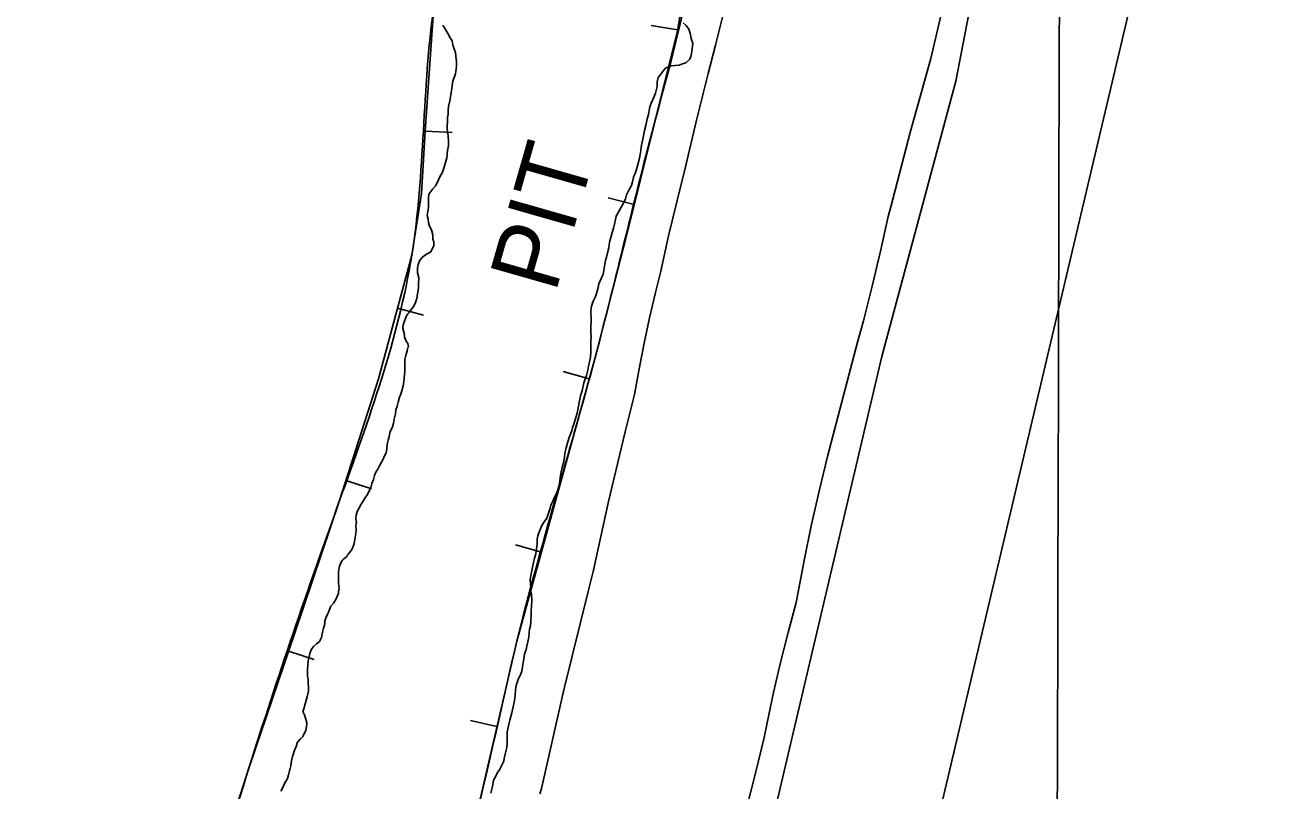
# Model space of a CAD drawing. Extents: x 3172297 to 3210190, y 958463 to 983887.
# Drawn here: x 3186026 to 3187191, y 968889 to 969598 of the extents above; entities that cross this region are included whole.
import ezdxf

# ---------------------------------------------------------------- set-up
doc = ezdxf.new("R2010")
doc.units = 0
for name, color, linetype in [('V-BORW-LINE', 7, 'Continuous'), ('V-GRID-MAJR', 7, 'Continuous'), ('V-LEVE-TOET', 7, 'Continuous'), ('V-RIVR-RANG', 7, 'Continuous'), ('V-TOPO-SHOR', 7, 'Continuous'), ('V-UTIL-LINE', 7, 'Continuous')]:
    doc.layers.add(name, color=color, linetype=linetype)

msp = doc.modelspace()

# ---------------------------------------------------------------- linework, layer by layer
at = {"layer": 'V-BORW-LINE'}
for p, q in [((3186630.3, 969593.9), (3186605.7, 969598.1)), ((3186396.5, 969500.2), (3186421.5, 969498.8)), ((3186590.1, 969432.2), (3186565.9, 969438.3)), ((3186370.8, 969336.2), (3186394.9, 969329.7)), ((3186548.5, 969270.9), (3186524.4, 969277.6)), ((3186323.1, 969176.6), (3186346.9, 969169)), ((3186504.1, 969110.3), (3186480, 969116.9)), ((3186269.9, 969018.7), (3186293.6, 969010.7)), ((3186463, 968948.9), (3186438.6, 968954.5))]:
    msp.add_line(p, q, dxfattribs=at)
for points in [[(3186372.5, 968107.6), (3186313.9, 968178.4), (3186306.5, 968191.2), (3186299.7, 968215.4), (3186298.6, 968234.5), (3186301.5, 968263.7), (3186307, 968292), (3186326, 968380), (3186345.5, 968468), (3186369.7, 968575.7), (3186394.3, 968683.3), (3186419.6, 968778.5), (3186445.6, 968873.5), (3186463.4, 968950.7), (3186481.5, 969027.9), (3186517.4, 969158.7), (3186553.6, 969289.4), (3186582.3, 969400.7), (3186610.1, 969512.4), (3186630.2, 969593.1), (3186644.2, 969674.8)], [(3186404.4, 969615.9), (3186396.6, 969500.3), (3186393.1, 969442.4), (3186384.1, 969385.4), (3186353.2, 969270.9), (3186317.2, 969158.1), (3186275.3, 969034.7), (3186233.5, 968911.2), (3186188.8, 968772.9), (3186144.3, 968634.5), (3186102.7, 968529.4), (3186058.5, 968423.3), (3186036.9, 968359.3), (3186030, 968327.1), (3186028.1, 968294.9), (3186030.2, 968274.3), (3186037.3, 968243.4), (3186046.2, 968212.5), (3186059.9, 968161.3), (3186068.2, 968136.4), (3186079.4, 968112.2), (3186104.8, 968072.6)]]:
    msp.add_lwpolyline(points, dxfattribs=at)
msp.add_spline([(3186570.9, 967823), (3186558.2, 967733.8), (3186525, 967688.7), (3186440.4, 967759.7), (3186332.5, 967843.6), (3186198.8, 967970), (3186079.4, 968112.2), (3186046.2, 968212.5), (3186028.1, 968294.9), (3186058.5, 968423.3), (3186144.3, 968634.5), (3186233.5, 968911.2), (3186317.2, 969158.1), (3186384.1, 969385.4), (3186404.4, 969615.9), (3186453, 969857.5), (3186463.9, 970055.1), (3186468.3, 970206), (3186442.7, 970412), (3186424.7, 970627), (3186444.1, 970707.7), (3186526.6, 970731.5), (3186576.5, 970720.7), (3186595.8, 970686.3), (3186618.9, 970575.1), (3186622.1, 970412), (3186626.9, 970258.7), (3186635, 970085.5), (3186634.7, 969845.8), (3186644.2, 969674.8), (3186610.1, 969512.4), (3186553.6, 969289.4), (3186481.5, 969027.9), (3186445.6, 968873.5), (3186394.3, 968683.3), (3186345.5, 968468), (3186307, 968292), (3186313.9, 968178.4), (3186434, 968043), (3186524.6, 967946.8), (3186572.1, 967882.8), (3186570.9, 967823)], degree=3, dxfattribs=at)
at = {"layer": 'V-GRID-MAJR'}
msp.add_spline([(3186968.9, 963893.7), (3186984.8, 969954), (3187000.7, 976017.3), (3187016.6, 982080.8), (3187016.6, 982083.8)], degree=3, dxfattribs=at)
at = {"layer": 'V-LEVE-TOET'}
for points in [[(3186892, 969683.8), (3186865, 969567.4), (3186865, 969567.4), (3186845.8, 969498.9), (3186827.8, 969430.1), (3186825.5, 969421.2), (3186825.5, 969421.2), (3186818.4, 969388.9), (3186810.7, 969356.7), (3186802.4, 969324.6)], [(3186502.6, 968886.4), (3186504.1, 968891.5), (3186504.1, 968891.5), (3186525, 968982.8), (3186547.4, 969073.9), (3186552.1, 969092.4), (3186552.1, 969092.4), (3186566.3, 969157.2), (3186581.7, 969221.7), (3186590.4, 969256.2), (3186590.4, 969256.2), (3186594.6, 969280), (3186599.3, 969303.7), (3186604.4, 969327.3), (3186610, 969350.8), (3186614.9, 969370.4), (3186614.9, 969370.4), (3186622, 969403.2), (3186629.8, 969435.9), (3186637.7, 969467.2), (3186637.7, 969467.2), (3186647.7, 969510.5), (3186658.5, 969553.7), (3186665.3, 969579.7), (3186665.3, 969579.7), (3186673.4, 969611.8)], [(3186802.4, 969324.6), (3186797, 969304.7), (3186797, 969304.7), (3186769.2, 969199), (3186769.2, 969199), (3186761.5, 969166.9), (3186754.2, 969134.7), (3186747.6, 969102.4), (3186741.5, 969070), (3186740.3, 969063.5), (3186740.3, 969063.5), (3186732.8, 969035.9), (3186725.8, 969008.2), (3186719.3, 968980.3), (3186713.3, 968952.3), (3186710.5, 968938.5), (3186710.5, 968938.5), (3186702.9, 968906.8), (3186694.8, 968875.2)]]:
    msp.add_lwpolyline(points, dxfattribs=at)
at = {"layer": 'V-TOPO-SHOR'}
for points in [[(3186924.2, 969734), (3186888, 969546.6), (3186819.5, 969291.4), (3186695, 968763.2), (3186594, 968374.2), (3186583.2, 968326.1), (3186581.4, 968302.9), (3186588.4, 968277.8), (3186599.1, 968254.6), (3186620.4, 968217.1), (3186700.6, 968145.4), (3186746.9, 968102.5), (3187032.1, 967889.3), (3187299.4, 967694), (3187871.5, 967251.6), (3187882.2, 967233.7), (3187869.6, 967214.1), (3187830.2, 967174.9)], [(3186404.6, 969397.6), (3186403.6, 969400.1), (3186403.6, 969400.9), (3186403.7, 969404.3), (3186402.3, 969408.7), (3186400.4, 969412.2), (3186399.6, 969415.6), (3186399.2, 969418.7), (3186398.4, 969422.1), (3186398.9, 969425.9), (3186399.4, 969429.4), (3186399.4, 969432.5), (3186399.5, 969438.2), (3186399.9, 969441.7), (3186401.8, 969444.2), (3186403.7, 969446.7), (3186406.1, 969449.4), (3186407.6, 969452.3), (3186408.8, 969455.2), (3186410.4, 969458.6), (3186412.3, 969461.5), (3186413.4, 969465), (3186414.4, 969468.2), (3186415.3, 969471.1), (3186416.4, 969475.5), (3186417.3, 969482.4), (3186418.2, 969486.5), (3186418.2, 969491.1), (3186417.9, 969495.1), (3186417.5, 969498.7), (3186416.7, 969501.6), (3186416.7, 969504.7), (3186417.2, 969509.3), (3186417.2, 969512.7), (3186417.9, 969515.8), (3186417.7, 969519.6), (3186418, 969522.9), (3186419.3, 969528.2), (3186419.8, 969532.1), (3186420.6, 969535.9), (3186421.3, 969539.8), (3186422.2, 969546.7), (3186423.3, 969549.9), (3186423.9, 969551.3), (3186424.6, 969553.6), (3186425.3, 969557.4), (3186425.5, 969560.9), (3186425.6, 969564.3), (3186424.8, 969569.5), (3186424.6, 969573.1), (3186423.6, 969575.4), (3186422.2, 969580), (3186421.4, 969583.8), (3186419.7, 969586.7), (3186417.1, 969591.2), (3186415.4, 969594.3), (3186412.8, 969598.5)], [(3186635.6, 969600.6), (3186638.3, 969597.9), (3186640.8, 969594.7), (3186642, 969590.9), (3186642.8, 969585.9), (3186644.4, 969581.3), (3186643.5, 969574), (3186642.8, 969570.4), (3186641.7, 969566.9), (3186637.9, 969563.4), (3186635, 969562.4), (3186631.8, 969561.3), (3186627.8, 969561), (3186624.3, 969560.6)], [(3186624.3, 969560.6), (3186623.9, 969560.6), (3186623.2, 969560.2), (3186620.9, 969559.6), (3186619.2, 969558.6), (3186617.1, 969556.1), (3186616.5, 969555.4), (3186612.4, 969549.8), (3186611.3, 969545.9), (3186611.3, 969541.5), (3186610, 969535.4), (3186608.7, 969532.3), (3186605.7, 969526.1), (3186604.6, 969522.7), (3186604.1, 969519.2), (3186603.3, 969515.6), (3186602.2, 969511.5), (3186600.8, 969505.4), (3186599.8, 969500.8), (3186599.1, 969497.3), (3186598, 969492.7), (3186597.1, 969488.9), (3186596.6, 969485.4), (3186596.2, 969482.2), (3186595.5, 969478.5), (3186595.1, 969475.1), (3186593.1, 969468), (3186591.8, 969463.9), (3186590.9, 969461), (3186589.4, 969458), (3186589.6, 969457.4), (3186588.5, 969453.2), (3186587.7, 969449.9), (3186585.5, 969446.2), (3186583, 969441.2), (3186581.9, 969437.4), (3186579.5, 969432.4), (3186578, 969429.7), (3186576.1, 969426.4), (3186573.5, 969421.4), (3186572.9, 969418.3), (3186572, 969414.1), (3186570.9, 969410.3), (3186569.8, 969406.2), (3186568.5, 969401.6), (3186567.6, 969398.7), (3186567, 969395.1), (3186566.7, 969392), (3186565.6, 969388.6), (3186564.3, 969383.4), (3186563.5, 969380.3), (3186563, 969377), (3186562.3, 969373), (3186561.4, 969367.8), (3186559.7, 969364.4), (3186557.4, 969358.8), (3186556.7, 969355.5), (3186555.6, 969350.7), (3186554.3, 969346.9), (3186552.4, 969343.2), (3186551.1, 969339.8), (3186550.2, 969336.9), (3186550, 969331.9), (3186550.1, 969327.7), (3186550.1, 969324.4), (3186549.8, 969318.3), (3186549.8, 969314.1), (3186550.1, 969309.3), (3186549.9, 969306), (3186550, 969301.1), (3186549.8, 969295.5), (3186549.7, 969290.9), (3186548.6, 969286.5), (3186547.9, 969282.5), (3186547.1, 969278.8), (3186546, 969273.8), (3186544.4, 969270), (3186543.6, 969267.1), (3186542, 969259.8), (3186540.5, 969255), (3186539.6, 969252.1), (3186539.2, 969249), (3186538.3, 969244), (3186537.4, 969238.9), (3186536.5, 969235.8), (3186534.2, 969228.7), (3186533.1, 969225.6), (3186532.2, 969222.7), (3186530, 969216.4), (3186528.5, 969212.3), (3186527, 969206.8), (3186525.9, 969201.8), (3186525.4, 969198.3), (3186525, 969194.3), (3186523.5, 969188.7), (3186522.6, 969184.7), (3186521.5, 969179.3), (3186521.2, 969175.9), (3186520.3, 969170.3), (3186520.3, 969169.5), (3186518, 969164.5)], [(3186312, 969063.2), (3186314.1, 969066.9), (3186315.4, 969070.1), (3186316.1, 969071.7), (3186316.3, 969073.6), (3186316.7, 969076.7), (3186316.2, 969081.6), (3186316.2, 969086.2), (3186316.3, 969092.2), (3186317.2, 969097.2), (3186318.3, 969100.4), (3186320, 969102.9), (3186321, 969104.1), (3186323.8, 969106.2), (3186324.8, 969108), (3186325.5, 969108.7), (3186328, 969111.8), (3186329.5, 969114.7), (3186330.8, 969118.2), (3186331.7, 969123.9), (3186332.2, 969127.4), (3186332.4, 969131.4), (3186332.2, 969134.5), (3186332.7, 969137.7), (3186332.3, 969141), (3186332.6, 969144.4), (3186333.4, 969147.9), (3186335.1, 969150.8), (3186337.3, 969154.6), (3186339.2, 969158.1), (3186341.3, 969161.2), (3186343, 969163.7), (3186344.5, 969167), (3186346, 969169.9), (3186347.1, 969173.9), (3186348.6, 969177.7), (3186349.5, 969181.4), (3186350.8, 969184.5), (3186352.5, 969187), (3186354.2, 969190.1), (3186355.9, 969193.7), (3186357.6, 969196.4), (3186358.9, 969199.5), (3186360.2, 969202.4), (3186361.1, 969205.6), (3186361.3, 969210.2), (3186362.2, 969214.1), (3186363.1, 969217.2), (3186363.8, 969221.2), (3186366.3, 969226.2), (3186367, 969229.8), (3186367.7, 969233.3), (3186369, 969238.5), (3186369.4, 969242.1), (3186370.5, 969245.4), (3186371.6, 969249.2), (3186372.7, 969253.8), (3186373.8, 969256.7), (3186375.1, 969261), (3186376.2, 969264.4), (3186376.8, 969267.7), (3186377.1, 969271.3), (3186377.3, 969274.8), (3186377.6, 969278), (3186377.6, 969281.3), (3186377.7, 969285.3), (3186377.7, 969288.8), (3186378.4, 969292.4), (3186379.7, 969296.6), (3186380.5, 969299.7), (3186381, 969300.5), (3186380.4, 969303.5), (3186378.5, 969306.4), (3186377.3, 969309.6), (3186376.9, 969313.1), (3186375.9, 969317.5), (3186376.2, 969320.7), (3186377.3, 969324.2), (3186379.2, 969329.2), (3186380.3, 969330.9), (3186381.5, 969332.1), (3186383.2, 969334.6), (3186385.4, 969337.3), (3186387.1, 969340.6), (3186388.8, 969345.2), (3186389.3, 969349.4), (3186389.9, 969352.7), (3186390.4, 969355.9), (3186390.2, 969359.2), (3186390.5, 969364.2), (3186389.5, 969369.1), (3186389.3, 969373.7), (3186390, 969376.8), (3186391.1, 969380.1), (3186393.4, 969382.8), (3186395.9, 969385.1), (3186398.9, 969386.9), (3186401.6, 969388.4), (3186403.1, 969391.1), (3186404.4, 969394), (3186404.6, 969397.6)], [(3186518, 969164.5), (3186516, 969160.5), (3186514.7, 969157.6), (3186513, 969153.8), (3186512.2, 969150.9), (3186510.9, 969147.2), (3186509.1, 969141.8), (3186506.6, 969138.4), (3186504.4, 969134.9), (3186503.2, 969132), (3186501.9, 969128.2), (3186500.8, 969125.3), (3186500.3, 969122.2), (3186500.1, 969117.2), (3186499.6, 969113.8), (3186498.9, 969108.6), (3186497.8, 969104.8), (3186496.3, 969098), (3186495.6, 969094.4), (3186494.3, 969088.6), (3186493.6, 969085), (3186494, 969081), (3186494.2, 969077.5), (3186494.3, 969074.1), (3186494.9, 969071), (3186495.3, 969065.8), (3186495, 969059.9), (3186494.8, 969056.3), (3186494.7, 969053.2), (3186494.4, 969045.9), (3186494, 969041.9), (3186493.1, 969038.8), (3186492.9, 969035.7), (3186492.6, 969031.5), (3186491.5, 969027.1), (3186490.6, 969023.3), (3186490, 969020.2), (3186488.7, 969016.7), (3186488.5, 969015.8), (3186487.8, 969011.7), (3186486.7, 969004.1), (3186486, 969000), (3186484.7, 968996.6), (3186483, 968993.3), (3186481.5, 968988.7), (3186480.6, 968985.6), (3186480.1, 968982.4), (3186479.7, 968977.6), (3186479.2, 968972.8), (3186478.7, 968969.7), (3186476.8, 968961.3), (3186475, 968954.7), (3186474.1, 968950.9), (3186473.5, 968947.8), (3186472.4, 968943.6), (3186472.3, 968940.3), (3186472.5, 968933.2), (3186472, 968929.4), (3186470.7, 968923.1), (3186469.8, 968919), (3186469.4, 968917.1), (3186468.9, 968916), (3186467.4, 968912.9), (3186465.3, 968908.5), (3186463.6, 968906.1), (3186461.5, 968902.3), (3186459.7, 968899.2), (3186459.1, 968895), (3186458.6, 968891.9), (3186457.3, 968886.9)], [(3186262.8, 968889), (3186264.5, 968892.4), (3186266.6, 968896.7), (3186269, 968900.7), (3186270, 968904), (3186270.9, 968907.8), (3186271.1, 968908.8), (3186272, 968912.4), (3186272.7, 968917), (3186273.6, 968920.9), (3186274.4, 968923.9), (3186275.7, 968927.4), (3186277, 968930.3), (3186278.3, 968934.3), (3186278.5, 968934.5), (3186280.7, 968937.2), (3186283, 968939.5), (3186284.5, 968942.2), (3186286, 968945.1), (3186286.6, 968948.6), (3186286.7, 968952.2), (3186285.7, 968956.6), (3186284.7, 968959.5), (3186283.2, 968962.7), (3186284.3, 968966.2), (3186284.8, 968967.5), (3186285.9, 968971.9), (3186287, 968976.4), (3186288.5, 968981.9), (3186288.5, 968985.4), (3186288.1, 968988.8), (3186288, 968991.9), (3186287.6, 968995.7), (3186287.6, 969000.9), (3186287.7, 969006.1), (3186288.4, 969011), (3186289.7, 969016.4), (3186291, 969019.7), (3186293.1, 969023), (3186295.7, 969025.5), (3186298.6, 969027.6), (3186300.3, 969031.1), (3186301.4, 969036.1), (3186302.3, 969039.9), (3186303.2, 969043), (3186303.4, 969043.6), (3186303.6, 969046.8), (3186305.2, 969050.9), (3186306.7, 969053.8), (3186307.7, 969057), (3186309.2, 969060.1), (3186312, 969063.2)]]:
    msp.add_lwpolyline(points, dxfattribs=at)
at = {"layer": 'V-UTIL-LINE'}
msp.add_lwpolyline([(3187111.3, 971559.6), (3187055.5, 969641.3), (3186187.8, 965968.4)], dxfattribs=at)

# ---------------------------------------------------------------- texts
at = {"layer": 'V-RIVR-RANG'}
msp.add_text(' PIT', height=64, rotation=74.0685, dxfattribs=at).set_placement((3186510.5, 969326.3))

doc.saveas('drawing.dxf')
